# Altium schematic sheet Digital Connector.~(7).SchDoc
size A
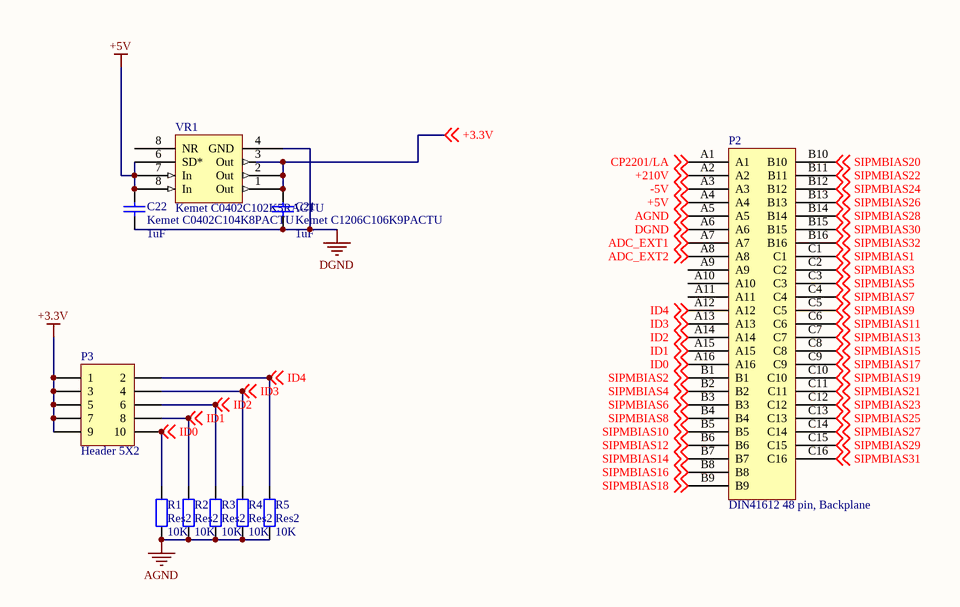
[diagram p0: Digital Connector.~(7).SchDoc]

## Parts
C21  Kemet C1206C106K9PACTU  value 1uF  [C1206]
C22  Kemet C0402C104K8PACTU  value 1uF  [C1206]
P2  DIN41612 48 pin, Backplane  [EURO2.54-2V48]
P3  Header 5X2  [HDR2X5]
R1  Res2  value 10K  [1005[0402]]
R2  Res2  value 10K  [1005[0402]]
R3  Res2  value 10K  [1005[0402]]
R4  Res2  value 10K  [1005[0402]]
R5  Res2  value 10K  [1005[0402]]
VR1  Kemet C0402C102K5RACTU  [RM-8]

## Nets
+3.3V: C21.2 P3.1 P3.3 P3.5 P3.7 P3.9 VR1.1(Out) VR1.2(Out) VR1.3(Out) ; off-sheet +3.3V
+5V: C22.2 P2.A4 VR1.6(SD*) VR1.7(In) VR1.8(In) ; off-sheet +5V
AGND: P2.A5 R1.1 R2.1 R3.1 R4.1 R5.1 ; off-sheet AGND
DGND: C21.1 C22.1 P2.A6 VR1.4(GND) ; off-sheet DGND
+210V: P2.A2 ; off-sheet +210V
-5V: P2.A3 ; off-sheet -5V
ADC_EXT1: P2.A7 ; off-sheet ADC_EXT1
ADC_EXT2: P2.A8 ; off-sheet ADC_EXT2
CP2201/LA: P2.A1 ; off-sheet CP2201/LA
ID0: P2.A16 P3.10 R1.2 ; off-sheet ID0
ID1: P2.A15 P3.8 R2.2 ; off-sheet ID1
ID2: P2.A14 P3.6 R3.2 ; off-sheet ID2
ID3: P2.A13 P3.4 R4.2 ; off-sheet ID3
ID4: P2.A12 P3.2 R5.2 ; off-sheet ID4
SIPMBIAS1: P2.C1 ; off-sheet SIPMBIAS1
SIPMBIAS2: P2.B1 ; off-sheet SIPMBIAS2
SIPMBIAS3: P2.C2 ; off-sheet SIPMBIAS3
SIPMBIAS4: P2.B2 ; off-sheet SIPMBIAS4
SIPMBIAS5: P2.C3 ; off-sheet SIPMBIAS5
SIPMBIAS6: P2.B3 ; off-sheet SIPMBIAS6
SIPMBIAS7: P2.C4 ; off-sheet SIPMBIAS7
SIPMBIAS8: P2.B4 ; off-sheet SIPMBIAS8
SIPMBIAS9: P2.C5 ; off-sheet SIPMBIAS9
SIPMBIAS10: P2.B5 ; off-sheet SIPMBIAS10
SIPMBIAS11: P2.C6 ; off-sheet SIPMBIAS11
SIPMBIAS12: P2.B6 ; off-sheet SIPMBIAS12
SIPMBIAS13: P2.C7 ; off-sheet SIPMBIAS13
SIPMBIAS14: P2.B7 ; off-sheet SIPMBIAS14
SIPMBIAS15: P2.C8 ; off-sheet SIPMBIAS15
SIPMBIAS16: P2.B8 ; off-sheet SIPMBIAS16
SIPMBIAS17: P2.C9 ; off-sheet SIPMBIAS17
SIPMBIAS18: P2.B9 ; off-sheet SIPMBIAS18
SIPMBIAS19: P2.C10 ; off-sheet SIPMBIAS19
SIPMBIAS20: P2.B10 ; off-sheet SIPMBIAS20
SIPMBIAS21: P2.C11 ; off-sheet SIPMBIAS21
SIPMBIAS22: P2.B11 ; off-sheet SIPMBIAS22
SIPMBIAS23: P2.C12 ; off-sheet SIPMBIAS23
SIPMBIAS24: P2.B12 ; off-sheet SIPMBIAS24
SIPMBIAS25: P2.C13 ; off-sheet SIPMBIAS25
SIPMBIAS26: P2.B13 ; off-sheet SIPMBIAS26
SIPMBIAS27: P2.C14 ; off-sheet SIPMBIAS27
SIPMBIAS28: P2.B14 ; off-sheet SIPMBIAS28
SIPMBIAS29: P2.C15 ; off-sheet SIPMBIAS29
SIPMBIAS30: P2.B15 ; off-sheet SIPMBIAS30
SIPMBIAS31: P2.C16 ; off-sheet SIPMBIAS31
SIPMBIAS32: P2.B16 ; off-sheet SIPMBIAS32

Not connected (* = marked no-connect by the designer): P2 A9 A10 A11

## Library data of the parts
C21 C22 = Cap: Capacitor
P3 = Header 5X2: Header, 5-Pin, Dual row
R1-R5 = Res2: Resistor
VR1 = ADP3335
